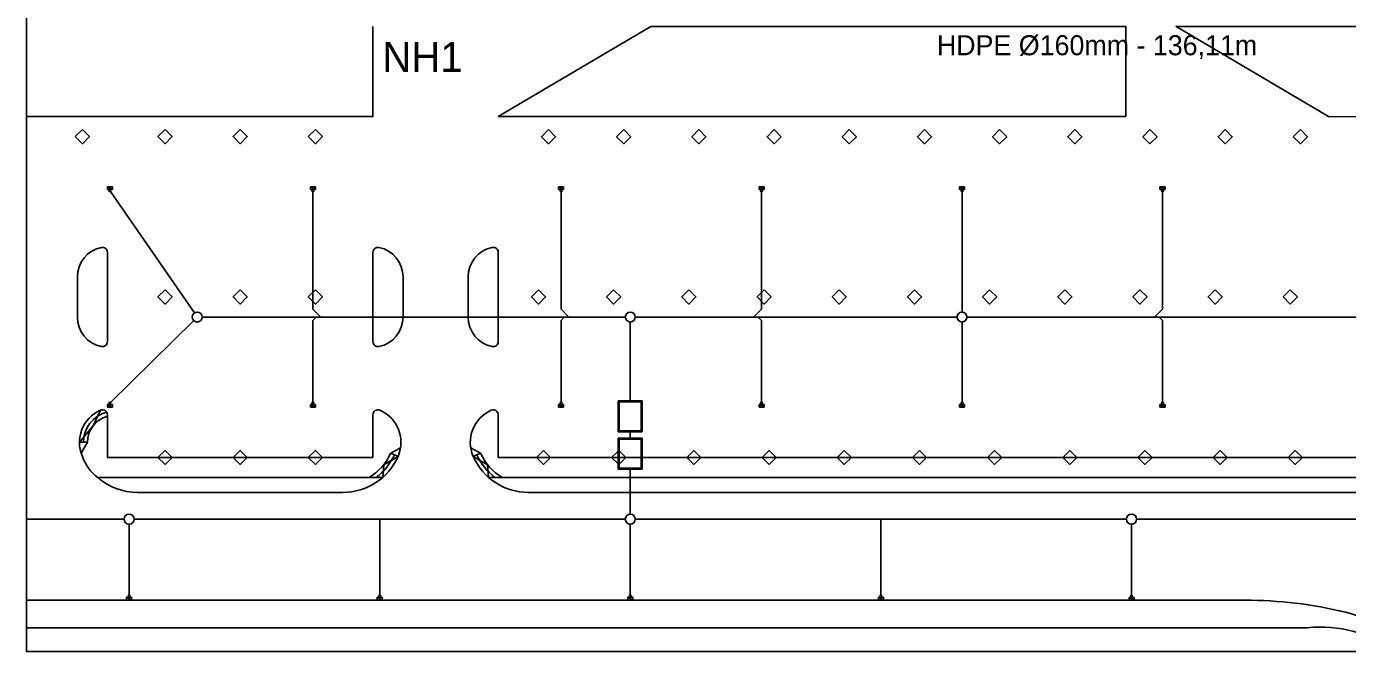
# Model space of a CAD drawing. Extents: x -263964 to -263544, y -1242317 to -1242020.
# Drawn here: x -263964.1 to -263832.4, y -1242317.4 to -1242255 of the extents above; entities that cross this region are included whole.
import ezdxf

# ---------------------------------------------------------------- set-up
doc = ezdxf.new("R2010")
doc.units = 0
for name, color, linetype in [('KFA_KOORDINACNA_SITUACIA_DSP_SEDA', 7, 'Continuous'), ('POPIS', 7, 'Continuous'), ('RAM_NA_TLAC_A3_1-100', 7, 'Continuous')]:
    doc.layers.add(name, color=color, linetype=linetype)

msp = doc.modelspace()

# ---------------------------------------------------------------- linework, layer by layer
at = {"layer": 'KFA_KOORDINACNA_SITUACIA_DSP_SEDA'}
for p, q in [((-263956.07, -1242270.98), (-263955.57, -1242270.98)), ((-263956.07, -1242271.27), (-263956.07, -1242270.98)), ((-263956.07, -1242270.98), (-263955.57, -1242271.27)), ((-263956.07, -1242270.98), (-263955.57, -1242271.27)), ((-263955.57, -1242270.98), (-263956.07, -1242270.98)), ((-263955.57, -1242271.27), (-263956.07, -1242271.27)), ((-263955.76, -1242271.45), (-263947.39, -1242283.57)), ((-263955.57, -1242270.98), (-263955.57, -1242271.27)), ((-263955.57, -1242271.27), (-263955.57, -1242270.98)), ((-263935.82, -1242270.98), (-263935.32, -1242270.98)), ((-263935.82, -1242271.27), (-263935.82, -1242270.98)), ((-263935.82, -1242270.98), (-263935.32, -1242271.27)), ((-263935.82, -1242270.98), (-263935.32, -1242271.27)), ((-263935.32, -1242270.98), (-263935.82, -1242270.98)), ((-263935.32, -1242271.27), (-263935.82, -1242271.27)), ((-263935.57, -1242271.47), (-263935.57, -1242283.19)), ((-263935.32, -1242270.98), (-263935.32, -1242271.27)), ((-263935.32, -1242271.27), (-263935.32, -1242270.98)), ((-263911.07, -1242270.98), (-263910.57, -1242270.98)), ((-263911.07, -1242271.27), (-263911.07, -1242270.98)), ((-263911.07, -1242270.98), (-263910.57, -1242271.27)), ((-263911.07, -1242270.98), (-263910.57, -1242271.27)), ((-263910.57, -1242270.98), (-263911.07, -1242270.98)), ((-263910.57, -1242271.27), (-263911.07, -1242271.27)), ((-263910.82, -1242271.47), (-263910.82, -1242283.19)), ((-263910.57, -1242270.98), (-263910.57, -1242271.27)), ((-263910.57, -1242271.27), (-263910.57, -1242270.98)), ((-263891.07, -1242270.98), (-263890.57, -1242270.98)), ((-263891.07, -1242271.27), (-263891.07, -1242270.98)), ((-263891.07, -1242270.98), (-263890.57, -1242271.27)), ((-263891.07, -1242270.98), (-263890.57, -1242271.27)), ((-263890.57, -1242270.98), (-263891.07, -1242270.98)), ((-263890.57, -1242271.27), (-263891.07, -1242271.27)), ((-263890.82, -1242271.47), (-263890.82, -1242283.19)), ((-263890.57, -1242270.98), (-263890.57, -1242271.27)), ((-263890.57, -1242271.27), (-263890.57, -1242270.98)), ((-263871.07, -1242270.98), (-263870.57, -1242270.98)), ((-263871.07, -1242271.27), (-263871.07, -1242270.98)), ((-263871.07, -1242270.98), (-263870.57, -1242271.27)), ((-263871.07, -1242270.98), (-263870.57, -1242271.27)), ((-263870.57, -1242270.98), (-263871.07, -1242270.98)), ((-263870.57, -1242271.27), (-263871.07, -1242271.27)), ((-263870.82, -1242271.47), (-263870.82, -1242283.48)), ((-263870.57, -1242270.98), (-263870.57, -1242271.27)), ((-263870.57, -1242271.27), (-263870.57, -1242270.98)), ((-263851.07, -1242270.98), (-263850.57, -1242270.98)), ((-263851.07, -1242271.27), (-263851.07, -1242270.98)), ((-263851.07, -1242270.98), (-263850.57, -1242271.27)), ((-263851.07, -1242270.98), (-263850.57, -1242271.27)), ((-263850.57, -1242270.98), (-263851.07, -1242270.98)), ((-263850.57, -1242271.27), (-263851.07, -1242271.27)), ((-263850.82, -1242271.47), (-263850.82, -1242283.19)), ((-263850.57, -1242270.98), (-263850.57, -1242271.27)), ((-263850.57, -1242271.27), (-263850.57, -1242270.98)), ((-263956.07, -1242286.43), (-263956.07, -1242277.53)), ((-263929.58, -1242286.43), (-263929.58, -1242277.53)), ((-263917.08, -1242286.43), (-263917.08, -1242277.53)), ((-263959.07, -1242279.98), (-263959.07, -1242283.98)), ((-263926.58, -1242283.98), (-263926.58, -1242279.98)), ((-263926.58, -1242280.48), (-263926.58, -1242283.98)), ((-263920.08, -1242279.98), (-263920.08, -1242283.98)), ((-263935.57, -1242283.19), (-263934.78, -1242283.98)), ((-263910.82, -1242283.19), (-263910.03, -1242283.98)), ((-263890.82, -1242283.19), (-263891.62, -1242283.98)), ((-263850.82, -1242283.19), (-263851.62, -1242283.98)), ((-263955.75, -1242292.52), (-263947.46, -1242284.33)), ((-263946.61, -1242283.98), (-263908.96, -1242283.98)), ((-263946.61, -1242283.98), (-263904.41, -1242283.98)), ((-263935.57, -1242284.34), (-263935.25, -1242283.98)), ((-263935.57, -1242292.49), (-263935.57, -1242284.34)), ((-263910.82, -1242284.34), (-263910.5, -1242283.98)), ((-263910.82, -1242292.49), (-263910.82, -1242284.34)), ((-263903.91, -1242284.48), (-263903.91, -1242292.35)), ((-263871.32, -1242283.98), (-263903.41, -1242283.98)), ((-263890.82, -1242284.34), (-263891.15, -1242283.98)), ((-263890.82, -1242292.49), (-263890.82, -1242284.34)), ((-263870.82, -1242292.49), (-263870.82, -1242284.48)), ((-263817.94, -1242283.98), (-263870.32, -1242283.98)), ((-263817.94, -1242283.98), (-263870.32, -1242283.98)), ((-263850.82, -1242284.34), (-263851.15, -1242283.98)), ((-263850.82, -1242292.49), (-263850.82, -1242284.34)), ((-263956.07, -1242292.69), (-263955.57, -1242292.69)), ((-263956.07, -1242292.98), (-263956.07, -1242292.69)), ((-263956.07, -1242292.69), (-263955.57, -1242292.98)), ((-263956.07, -1242292.69), (-263955.57, -1242292.98)), ((-263955.57, -1242292.69), (-263956.07, -1242292.69)), ((-263955.57, -1242292.69), (-263955.57, -1242292.98)), ((-263955.57, -1242292.98), (-263955.57, -1242292.69)), ((-263935.82, -1242292.69), (-263935.32, -1242292.69)), ((-263935.82, -1242292.98), (-263935.82, -1242292.69)), ((-263935.82, -1242292.69), (-263935.32, -1242292.98)), ((-263935.82, -1242292.69), (-263935.32, -1242292.98)), ((-263935.32, -1242292.69), (-263935.82, -1242292.69)), ((-263935.32, -1242292.69), (-263935.32, -1242292.98)), ((-263935.32, -1242292.98), (-263935.32, -1242292.69)), ((-263911.07, -1242292.69), (-263910.57, -1242292.69)), ((-263911.07, -1242292.98), (-263911.07, -1242292.69)), ((-263911.07, -1242292.69), (-263910.57, -1242292.98)), ((-263911.07, -1242292.69), (-263910.57, -1242292.98)), ((-263910.57, -1242292.69), (-263911.07, -1242292.69)), ((-263910.57, -1242292.69), (-263910.57, -1242292.98)), ((-263910.57, -1242292.98), (-263910.57, -1242292.69)), ((-263905.11, -1242292.35), (-263902.71, -1242292.35)), ((-263905.11, -1242295.45), (-263905.11, -1242292.35)), ((-263905.01, -1242292.45), (-263902.81, -1242292.45)), ((-263905.01, -1242295.35), (-263905.01, -1242292.45)), ((-263902.81, -1242292.45), (-263902.81, -1242295.35)), ((-263902.71, -1242292.35), (-263902.71, -1242295.45)), ((-263891.07, -1242292.69), (-263890.57, -1242292.69)), ((-263891.07, -1242292.98), (-263891.07, -1242292.69)), ((-263891.07, -1242292.69), (-263890.57, -1242292.98)), ((-263891.07, -1242292.69), (-263890.57, -1242292.98)), ((-263890.57, -1242292.69), (-263891.07, -1242292.69)), ((-263890.57, -1242292.69), (-263890.57, -1242292.98)), ((-263890.57, -1242292.98), (-263890.57, -1242292.69)), ((-263871.07, -1242292.69), (-263870.57, -1242292.69)), ((-263871.07, -1242292.98), (-263871.07, -1242292.69)), ((-263871.07, -1242292.69), (-263870.57, -1242292.98)), ((-263871.07, -1242292.69), (-263870.57, -1242292.98)), ((-263870.57, -1242292.69), (-263871.07, -1242292.69)), ((-263870.57, -1242292.69), (-263870.57, -1242292.98)), ((-263870.57, -1242292.98), (-263870.57, -1242292.69)), ((-263851.07, -1242292.69), (-263850.57, -1242292.69)), ((-263851.07, -1242292.98), (-263851.07, -1242292.69)), ((-263851.07, -1242292.69), (-263850.57, -1242292.98)), ((-263851.07, -1242292.69), (-263850.57, -1242292.98)), ((-263850.57, -1242292.69), (-263851.07, -1242292.69)), ((-263850.57, -1242292.69), (-263850.57, -1242292.98)), ((-263850.57, -1242292.98), (-263850.57, -1242292.69)), ((-263955.57, -1242292.98), (-263956.07, -1242292.98)), ((-263956.07, -1242297.98), (-263956.07, -1242293.74)), ((-263935.32, -1242292.98), (-263935.82, -1242292.98)), ((-263929.58, -1242297.98), (-263929.58, -1242293.74)), ((-263917.08, -1242293.74), (-263917.08, -1242297.98)), ((-263910.57, -1242292.98), (-263911.07, -1242292.98)), ((-263890.57, -1242292.98), (-263891.07, -1242292.98)), ((-263870.57, -1242292.98), (-263871.07, -1242292.98)), ((-263850.57, -1242292.98), (-263851.07, -1242292.98)), ((-263905.11, -1242295.45), (-263902.71, -1242295.45)), ((-263905.01, -1242295.35), (-263902.81, -1242295.35)), ((-263903.91, -1242295.45), (-263903.91, -1242296.05)), ((-263905.11, -1242299.15), (-263905.11, -1242296.05)), ((-263902.71, -1242296.05), (-263905.11, -1242296.05)), ((-263902.81, -1242296.15), (-263905.01, -1242296.15)), ((-263905.01, -1242299.05), (-263905.01, -1242296.15)), ((-263902.81, -1242296.15), (-263902.81, -1242299.05)), ((-263902.71, -1242296.05), (-263902.71, -1242299.15)), ((-263929.58, -1242297.98), (-263956.07, -1242297.98)), ((-263927.81, -1242297.56), (-263926.83, -1242297.03)), ((-263927.81, -1242297.56), (-263927.08, -1242297.88)), ((-263918.85, -1242297.56), (-263919.83, -1242297.03)), ((-263918.85, -1242297.56), (-263919.58, -1242297.88)), ((-263815.6, -1242297.98), (-263917.08, -1242297.98)), ((-263902.71, -1242299.15), (-263905.11, -1242299.15)), ((-263902.81, -1242299.05), (-263905.01, -1242299.05)), ((-263903.91, -1242299.15), (-263903.91, -1242303.65)), ((-263928.61, -1242299.98), (-263957.04, -1242299.98)), ((-263816.31, -1242299.98), (-263918.05, -1242299.98)), ((-263932.58, -1242301.48), (-263953.07, -1242301.48)), ((-263914.08, -1242301.48), (-263815.82, -1242301.48)), ((-263954.41, -1242304.15), (-263964.15, -1242304.15)), ((-263953.91, -1242311.74), (-263953.91, -1242304.65)), ((-263904.41, -1242304.15), (-263953.41, -1242304.15)), ((-263928.91, -1242311.74), (-263928.91, -1242304.15)), ((-263903.91, -1242311.74), (-263903.91, -1242304.65)), ((-263854.41, -1242304.15), (-263903.41, -1242304.15)), ((-263878.91, -1242311.74), (-263878.91, -1242304.15)), ((-263853.91, -1242311.75), (-263853.91, -1242304.65)), ((-263809.09, -1242304.15), (-263853.41, -1242304.15)), ((-263964.15, -1242312.23), (-263857.33, -1242312.23)), ((-263954.16, -1242311.94), (-263953.66, -1242311.94)), ((-263954.16, -1242312.23), (-263954.16, -1242311.94)), ((-263954.16, -1242311.94), (-263953.66, -1242312.23)), ((-263954.16, -1242311.94), (-263953.66, -1242312.23)), ((-263953.66, -1242311.94), (-263954.16, -1242311.94)), ((-263953.66, -1242312.23), (-263954.16, -1242312.23)), ((-263953.66, -1242311.94), (-263953.66, -1242312.23)), ((-263953.66, -1242312.23), (-263953.66, -1242311.94)), ((-263929.16, -1242311.94), (-263928.66, -1242311.94)), ((-263929.16, -1242312.23), (-263929.16, -1242311.94)), ((-263929.16, -1242311.94), (-263928.66, -1242312.23)), ((-263929.16, -1242311.94), (-263928.66, -1242312.23)), ((-263928.66, -1242311.94), (-263929.16, -1242311.94)), ((-263928.66, -1242312.23), (-263929.16, -1242312.23)), ((-263928.66, -1242311.94), (-263928.66, -1242312.23)), ((-263928.66, -1242312.23), (-263928.66, -1242311.94)), ((-263842.6, -1242312.24), (-263924.19, -1242312.23)), ((-263904.16, -1242311.94), (-263903.66, -1242311.94)), ((-263904.16, -1242312.23), (-263904.16, -1242311.94)), ((-263904.16, -1242311.94), (-263903.66, -1242312.23)), ((-263904.16, -1242311.94), (-263903.66, -1242312.23)), ((-263903.66, -1242311.94), (-263904.16, -1242311.94)), ((-263903.66, -1242312.23), (-263904.16, -1242312.23)), ((-263903.66, -1242311.94), (-263903.66, -1242312.23)), ((-263903.66, -1242312.23), (-263903.66, -1242311.94)), ((-263879.16, -1242311.94), (-263878.66, -1242311.94)), ((-263879.16, -1242312.23), (-263879.16, -1242311.94)), ((-263879.16, -1242311.94), (-263878.66, -1242312.23)), ((-263879.16, -1242311.94), (-263878.66, -1242312.23)), ((-263878.66, -1242311.94), (-263879.16, -1242311.94)), ((-263878.66, -1242312.23), (-263879.16, -1242312.23)), ((-263878.66, -1242311.94), (-263878.66, -1242312.23)), ((-263878.66, -1242312.23), (-263878.66, -1242311.94)), ((-263854.16, -1242311.95), (-263853.66, -1242311.95)), ((-263854.16, -1242312.24), (-263854.16, -1242311.95)), ((-263854.16, -1242311.95), (-263853.66, -1242312.24)), ((-263854.16, -1242311.95), (-263853.66, -1242312.24)), ((-263853.66, -1242311.95), (-263854.16, -1242311.95)), ((-263853.66, -1242312.24), (-263854.16, -1242312.24)), ((-263853.66, -1242311.95), (-263853.66, -1242312.24)), ((-263853.66, -1242312.24), (-263853.66, -1242311.95)), ((-263964.15, -1242314.98), (-263836.4, -1242314.98))]:
    msp.add_line(p, q, dxfattribs=at)
for points in [[(-263964.15, -1242263.98), (-263929.58, -1242263.98), (-263929.58, -1242254.98)], [(-263854.47, -1242263.98), (-263917.08, -1242263.98), (-263901.87, -1242254.98), (-263854.47, -1242254.98), (-263854.47, -1242263.98)], [(-263958.86, -1242296.48), (-263957.5, -1242294.84), (-263956.76, -1242293.27)], [(-263958.86, -1242296.48), (-263958.06, -1242296.48), (-263958.69, -1242297.56)], [(-263927.08, -1242297.88), (-263928.51, -1242298.71), (-263928.61, -1242299.98)], [(-263919.58, -1242297.88), (-263918.15, -1242298.71), (-263918.05, -1242299.98)]]:
    msp.add_lwpolyline(points, dxfattribs=at)
for points in [[(-263802.07, -1242263.99), (-263834.26, -1242263.98), (-263849.47, -1242254.98), (-263802.07, -1242254.99)], [(-263958.57, -1242265.28), (-263957.86, -1242265.98), (-263958.57, -1242266.69), (-263959.27, -1242265.98)], [(-263950.32, -1242265.28), (-263949.62, -1242265.98), (-263950.32, -1242266.69), (-263951.03, -1242265.98)], [(-263942.82, -1242265.28), (-263942.12, -1242265.98), (-263942.82, -1242266.69), (-263943.53, -1242265.98)], [(-263935.32, -1242265.28), (-263934.62, -1242265.98), (-263935.32, -1242266.69), (-263936.03, -1242265.98)], [(-263912.07, -1242265.28), (-263911.36, -1242265.99), (-263912.07, -1242266.69), (-263912.77, -1242265.99)], [(-263904.57, -1242265.28), (-263903.86, -1242265.99), (-263904.57, -1242266.69), (-263905.27, -1242265.99)], [(-263897.07, -1242265.28), (-263896.36, -1242265.99), (-263897.07, -1242266.69), (-263897.77, -1242265.99)], [(-263897.07, -1242265.28), (-263896.36, -1242265.99), (-263897.07, -1242266.69), (-263897.77, -1242265.99)], [(-263889.57, -1242265.28), (-263888.86, -1242265.99), (-263889.57, -1242266.69), (-263890.27, -1242265.99)], [(-263882.07, -1242265.28), (-263881.36, -1242265.99), (-263882.07, -1242266.69), (-263882.77, -1242265.99)], [(-263874.57, -1242265.28), (-263873.86, -1242265.99), (-263874.57, -1242266.69), (-263875.27, -1242265.99)], [(-263867.07, -1242265.28), (-263866.36, -1242265.99), (-263867.07, -1242266.69), (-263867.77, -1242265.99)], [(-263859.57, -1242265.28), (-263858.86, -1242265.99), (-263859.57, -1242266.69), (-263860.27, -1242265.99)], [(-263852.07, -1242265.28), (-263851.36, -1242265.99), (-263852.07, -1242266.69), (-263852.77, -1242265.99)], [(-263844.57, -1242265.28), (-263843.86, -1242265.99), (-263844.57, -1242266.69), (-263845.27, -1242265.99)], [(-263837.07, -1242265.28), (-263836.36, -1242265.99), (-263837.07, -1242266.69), (-263837.77, -1242265.99)], [(-263950.32, -1242281.28), (-263949.62, -1242281.98), (-263950.32, -1242282.69), (-263951.03, -1242281.98)], [(-263942.82, -1242281.28), (-263942.12, -1242281.98), (-263942.82, -1242282.69), (-263943.53, -1242281.98)], [(-263935.32, -1242281.28), (-263934.62, -1242281.98), (-263935.32, -1242282.69), (-263936.03, -1242281.98)], [(-263913.07, -1242281.28), (-263912.36, -1242281.98), (-263913.07, -1242282.69), (-263913.77, -1242281.98)], [(-263905.57, -1242281.28), (-263904.86, -1242281.98), (-263905.57, -1242282.69), (-263906.27, -1242281.98)], [(-263898.07, -1242281.28), (-263897.36, -1242281.98), (-263898.07, -1242282.69), (-263898.77, -1242281.98)], [(-263890.57, -1242281.28), (-263889.86, -1242281.98), (-263890.57, -1242282.69), (-263891.27, -1242281.98)], [(-263890.57, -1242281.28), (-263889.86, -1242281.98), (-263890.57, -1242282.69), (-263891.27, -1242281.98)], [(-263883.07, -1242281.28), (-263882.36, -1242281.98), (-263883.07, -1242282.69), (-263883.77, -1242281.98)], [(-263875.57, -1242281.28), (-263874.86, -1242281.98), (-263875.57, -1242282.69), (-263876.27, -1242281.98)], [(-263868.07, -1242281.28), (-263867.36, -1242281.98), (-263868.07, -1242282.69), (-263868.77, -1242281.98)], [(-263860.57, -1242281.28), (-263859.86, -1242281.98), (-263860.57, -1242282.69), (-263861.27, -1242281.98)], [(-263853.07, -1242281.28), (-263852.36, -1242281.98), (-263853.07, -1242282.69), (-263853.77, -1242281.98)], [(-263845.57, -1242281.28), (-263844.86, -1242281.98), (-263845.57, -1242282.69), (-263846.27, -1242281.98)], [(-263838.07, -1242281.28), (-263837.36, -1242281.98), (-263838.07, -1242282.69), (-263838.77, -1242281.98)], [(-263949.62, -1242297.98), (-263950.32, -1242297.28), (-263951.03, -1242297.98), (-263950.32, -1242298.69)], [(-263942.12, -1242297.98), (-263942.82, -1242297.28), (-263943.53, -1242297.98), (-263942.82, -1242298.69)], [(-263934.62, -1242297.98), (-263935.32, -1242297.28), (-263936.03, -1242297.98), (-263935.32, -1242298.69)], [(-263912.57, -1242297.28), (-263911.86, -1242297.98), (-263912.57, -1242298.69), (-263913.27, -1242297.98)], [(-263905.07, -1242297.28), (-263904.36, -1242297.98), (-263905.07, -1242298.69), (-263905.77, -1242297.98)], [(-263897.57, -1242297.28), (-263896.86, -1242297.98), (-263897.57, -1242298.69), (-263898.27, -1242297.98)], [(-263890.07, -1242297.28), (-263889.36, -1242297.98), (-263890.07, -1242298.69), (-263890.77, -1242297.98)], [(-263890.07, -1242297.28), (-263889.36, -1242297.98), (-263890.07, -1242298.69), (-263890.77, -1242297.98)], [(-263882.57, -1242297.28), (-263881.86, -1242297.98), (-263882.57, -1242298.69), (-263883.27, -1242297.98)], [(-263875.07, -1242297.28), (-263874.36, -1242297.98), (-263875.07, -1242298.69), (-263875.77, -1242297.98)], [(-263867.57, -1242297.28), (-263866.86, -1242297.98), (-263867.57, -1242298.69), (-263868.27, -1242297.98)], [(-263860.07, -1242297.28), (-263859.36, -1242297.98), (-263860.07, -1242298.69), (-263860.77, -1242297.98)], [(-263852.57, -1242297.28), (-263851.86, -1242297.98), (-263852.57, -1242298.69), (-263853.27, -1242297.98)], [(-263845.07, -1242297.28), (-263844.36, -1242297.98), (-263845.07, -1242298.69), (-263845.77, -1242297.98)], [(-263837.57, -1242297.28), (-263836.86, -1242297.98), (-263837.57, -1242298.69), (-263838.27, -1242297.98)]]:
    msp.add_lwpolyline(points, close=True, dxfattribs=at)
for centre, radius in [((-263955.82, -1242271.37), 0.1), ((-263935.57, -1242271.37), 0.1), ((-263910.82, -1242271.37), 0.1), ((-263890.82, -1242271.37), 0.1), ((-263870.82, -1242271.37), 0.1), ((-263850.82, -1242271.37), 0.1), ((-263947.11, -1242283.98), 0.5), ((-263903.91, -1242283.98), 0.5), ((-263870.82, -1242283.98), 0.5), ((-263955.82, -1242292.59), 0.1), ((-263935.57, -1242292.59), 0.1), ((-263910.82, -1242292.59), 0.1), ((-263890.82, -1242292.59), 0.1), ((-263870.82, -1242292.59), 0.1), ((-263850.82, -1242292.59), 0.1), ((-263953.91, -1242304.15), 0.5), ((-263903.91, -1242304.15), 0.5), ((-263853.91, -1242304.15), 0.5), ((-263953.91, -1242311.84), 0.1), ((-263928.91, -1242311.84), 0.1), ((-263903.91, -1242311.84), 0.1), ((-263878.91, -1242311.84), 0.1), ((-263853.91, -1242311.85), 0.1)]:
    msp.add_circle(centre, radius, dxfattribs=at)
for centre, radius, start, end in [((-263956.07, -1242279.98), 3, 101.537, 180), ((-263956.57, -1242277.53), 0.5, 0, 101.537), ((-263929.08, -1242277.53), 0.5, 78.463, 180), ((-263929.58, -1242279.98), 3, 0, 78.463), ((-263917.08, -1242279.98), 3, 101.537, 180), ((-263917.58, -1242277.53), 0.5, 0, 101.537), ((-263956.07, -1242283.98), 3, 180, 258.463), ((-263929.58, -1242283.98), 3, 281.537, 0), ((-263917.08, -1242283.98), 3, 180, 258.463), ((-263956.57, -1242286.43), 0.5, 258.463, 0), ((-263929.08, -1242286.43), 0.5, 180, 281.537), ((-263917.58, -1242286.43), 0.5, 258.463, 0), ((-263955.36, -1242296.48), 3.5, 113.7599, 203.5782), ((-263955.36, -1242296.48), 3.1, 104.5457, 180), ((-263955.36, -1242296.48), 2.7, 105.2176, 180), ((-263956.57, -1242293.74), 0.5, 0, 113.7599), ((-263929.08, -1242293.74), 0.5, 66.2401, 180), ((-263930.29, -1242296.48), 3.5, 336.4218, 66.2401), ((-263916.37, -1242296.48), 3.5, 113.7599, 203.5782), ((-263917.58, -1242293.74), 0.5, 0, 113.7599), ((-263954.44, -1242296.49), 4.35, 198.7173, 233.4513), ((-263932.58, -1242295.48), 6, 270, 336.4218), ((-263932.58, -1242295.48), 5.2, 300.0733, 336.4218), ((-263932.58, -1242295.48), 5.6, 306.5275, 336.4218), ((-263914.08, -1242295.48), 6, 203.5782, 270), ((-263914.08, -1242295.48), 5.6, 203.5782, 233.4725), ((-263914.08, -1242295.48), 5.2, 203.5782, 239.9267), ((-263953.07, -1242295.48), 6, 228.5904, 270), ((-263842.43, -1242353.35), 41.11, 76.1362, 90.2415), ((-263836.18, -1242329.03), 16, 46.8133, 76.9695), ((-263835.04, -1242327.71), 12.8, 53.9713, 96.0874)]:
    msp.add_arc(centre, radius, start, end, dxfattribs=at)
at = {"layer": 'RAM_NA_TLAC_A3_1-100'}
msp.add_lwpolyline([(-263964.15, -1242020.36), (-263544.15, -1242020.36), (-263544.15, -1242317.36), (-263964.15, -1242317.36)], close=True, dxfattribs=at)

# ---------------------------------------------------------------- texts
at = {"layer": 'POPIS'}
for s, height, p in [('HDPE Ø160mm - 136,11m', 2, (-263873.33, -1242257.86)), ('NH1', 3, (-263928.65, -1242259.54))]:
    msp.add_text(s, height=height, dxfattribs=at).set_placement(p)

doc.saveas('drawing.dxf')
